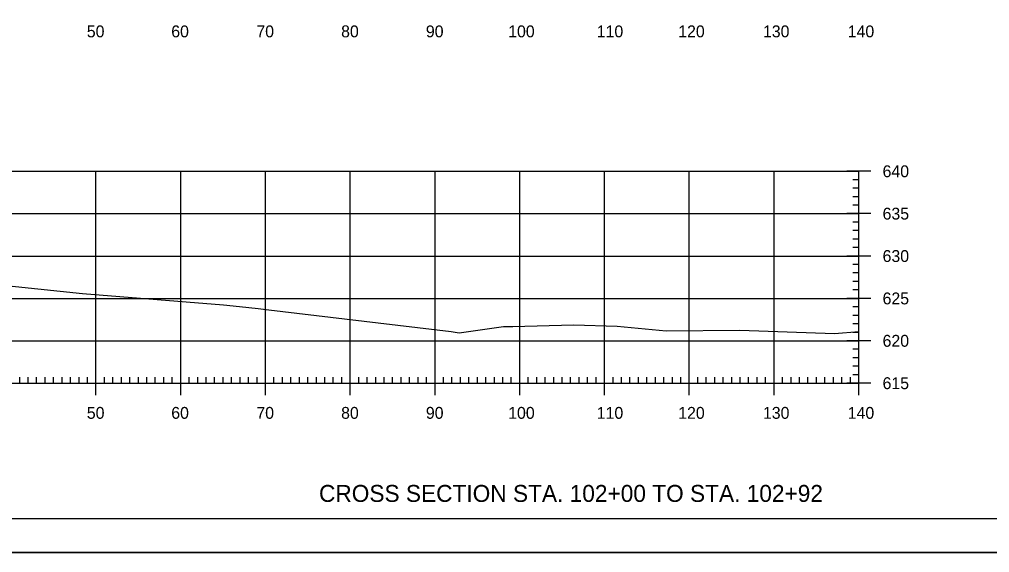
# Model space of a CAD drawing. Extents: x 1381471 to 1382703, y 370300 to 371487.
# Drawn here: x 1382177.6 to 1382292, y 370633.8 to 370696.7 of the extents above; entities that cross this region are included whole.
import ezdxf

# ---------------------------------------------------------------- set-up
doc = ezdxf.new("R2010")
doc.units = 0
doc.layers.add('Level 45', color=7, linetype='Continuous')

msp = doc.modelspace()

# ---------------------------------------------------------------- linework, layer by layer
at = {"layer": 'Level 45'}
for p, q in [((1381996.61, 370678.78), (1382276.61, 370678.78)), ((1382186.61, 370653.78), (1382186.61, 370678.78)), ((1382196.61, 370653.78), (1382196.61, 370678.78)), ((1382206.61, 370653.78), (1382206.61, 370678.78)), ((1382216.61, 370653.78), (1382216.61, 370678.78)), ((1382226.61, 370653.78), (1382226.61, 370678.78)), ((1382236.61, 370653.78), (1382236.61, 370678.78)), ((1382246.61, 370653.78), (1382246.61, 370678.78)), ((1382256.61, 370653.78), (1382256.61, 370678.78)), ((1382266.61, 370653.78), (1382266.61, 370678.78)), ((1382278.01, 370678.78), (1382275.21, 370678.78)), ((1382276.61, 370653.78), (1382276.61, 370678.78)), ((1382276.61, 370653.78), (1382276.61, 370678.78)), ((1382276.61, 370677.78), (1382275.91, 370677.78)), ((1382276.61, 370676.78), (1382275.91, 370676.78)), ((1382276.61, 370675.78), (1382275.91, 370675.78)), ((1382276.61, 370674.78), (1382275.91, 370674.78)), ((1381996.61, 370673.78), (1382276.61, 370673.78)), ((1382278.01, 370673.78), (1382275.21, 370673.78)), ((1382276.61, 370672.78), (1382275.91, 370672.78)), ((1382276.61, 370671.78), (1382275.91, 370671.78)), ((1382276.61, 370670.78), (1382275.91, 370670.78)), ((1382276.61, 370669.78), (1382275.91, 370669.78)), ((1381996.61, 370668.78), (1382276.61, 370668.78)), ((1382278.01, 370668.78), (1382275.21, 370668.78)), ((1382276.61, 370667.78), (1382275.91, 370667.78)), ((1382276.61, 370666.78), (1382275.91, 370666.78)), ((1382276.61, 370665.78), (1382275.91, 370665.78)), ((1382276.61, 370664.78), (1382275.91, 370664.78)), ((1381996.61, 370663.78), (1382276.61, 370663.78)), ((1382278.01, 370663.78), (1382275.21, 370663.78)), ((1382276.61, 370662.78), (1382275.91, 370662.78)), ((1382276.61, 370661.78), (1382275.91, 370661.78)), ((1382276.61, 370660.78), (1382275.91, 370660.78)), ((1382276.61, 370659.78), (1382275.91, 370659.78)), ((1381996.61, 370658.78), (1382276.61, 370658.78)), ((1382278.01, 370658.78), (1382275.21, 370658.78)), ((1382276.61, 370657.78), (1382275.91, 370657.78)), ((1382276.61, 370656.78), (1382275.91, 370656.78)), ((1382186.61, 370652.38), (1382186.61, 370655.18)), ((1382196.61, 370652.38), (1382196.61, 370655.18)), ((1382206.61, 370652.38), (1382206.61, 370655.18)), ((1382216.61, 370652.38), (1382216.61, 370655.18)), ((1382226.61, 370652.38), (1382226.61, 370655.18)), ((1382236.61, 370652.38), (1382236.61, 370655.18)), ((1382246.61, 370652.38), (1382246.61, 370655.18)), ((1382256.61, 370652.38), (1382256.61, 370655.18)), ((1382266.61, 370652.38), (1382266.61, 370655.18)), ((1382276.61, 370655.78), (1382275.91, 370655.78)), ((1382276.61, 370654.78), (1382275.91, 370654.78)), ((1382276.61, 370652.38), (1382276.61, 370655.18)), ((1381996.61, 370653.78), (1382276.61, 370653.78)), ((1381996.61, 370653.78), (1382276.61, 370653.78)), ((1382177.61, 370653.78), (1382177.61, 370654.48)), ((1382178.61, 370653.78), (1382178.61, 370654.48)), ((1382179.61, 370653.78), (1382179.61, 370654.48)), ((1382180.61, 370653.78), (1382180.61, 370654.48)), ((1382181.61, 370653.78), (1382181.61, 370654.48)), ((1382182.61, 370653.78), (1382182.61, 370654.48)), ((1382183.61, 370653.78), (1382183.61, 370654.48)), ((1382184.61, 370653.78), (1382184.61, 370654.48)), ((1382185.61, 370653.78), (1382185.61, 370654.48)), ((1382187.61, 370653.78), (1382187.61, 370654.48)), ((1382188.61, 370653.78), (1382188.61, 370654.48)), ((1382189.61, 370653.78), (1382189.61, 370654.48)), ((1382190.61, 370653.78), (1382190.61, 370654.48)), ((1382191.61, 370653.78), (1382191.61, 370654.48)), ((1382192.61, 370653.78), (1382192.61, 370654.48)), ((1382193.61, 370653.78), (1382193.61, 370654.48)), ((1382194.61, 370653.78), (1382194.61, 370654.48)), ((1382195.61, 370653.78), (1382195.61, 370654.48)), ((1382197.61, 370653.78), (1382197.61, 370654.48)), ((1382198.61, 370653.78), (1382198.61, 370654.48)), ((1382199.61, 370653.78), (1382199.61, 370654.48)), ((1382200.61, 370653.78), (1382200.61, 370654.48)), ((1382201.61, 370653.78), (1382201.61, 370654.48)), ((1382202.61, 370653.78), (1382202.61, 370654.48)), ((1382203.61, 370653.78), (1382203.61, 370654.48)), ((1382204.61, 370653.78), (1382204.61, 370654.48)), ((1382205.61, 370653.78), (1382205.61, 370654.48)), ((1382207.61, 370653.78), (1382207.61, 370654.48)), ((1382208.61, 370653.78), (1382208.61, 370654.48)), ((1382209.61, 370653.78), (1382209.61, 370654.48)), ((1382210.61, 370653.78), (1382210.61, 370654.48)), ((1382211.61, 370653.78), (1382211.61, 370654.48)), ((1382212.61, 370653.78), (1382212.61, 370654.48)), ((1382213.61, 370653.78), (1382213.61, 370654.48)), ((1382214.61, 370653.78), (1382214.61, 370654.48)), ((1382215.61, 370653.78), (1382215.61, 370654.48)), ((1382217.61, 370653.78), (1382217.61, 370654.48)), ((1382218.61, 370653.78), (1382218.61, 370654.48)), ((1382219.61, 370653.78), (1382219.61, 370654.48)), ((1382220.61, 370653.78), (1382220.61, 370654.48)), ((1382221.61, 370653.78), (1382221.61, 370654.48)), ((1382222.61, 370653.78), (1382222.61, 370654.48)), ((1382223.61, 370653.78), (1382223.61, 370654.48)), ((1382224.61, 370653.78), (1382224.61, 370654.48)), ((1382225.61, 370653.78), (1382225.61, 370654.48)), ((1382227.61, 370653.78), (1382227.61, 370654.48)), ((1382228.61, 370653.78), (1382228.61, 370654.48)), ((1382229.61, 370653.78), (1382229.61, 370654.48)), ((1382230.61, 370653.78), (1382230.61, 370654.48)), ((1382231.61, 370653.78), (1382231.61, 370654.48)), ((1382232.61, 370653.78), (1382232.61, 370654.48)), ((1382233.61, 370653.78), (1382233.61, 370654.48)), ((1382234.61, 370653.78), (1382234.61, 370654.48)), ((1382235.61, 370653.78), (1382235.61, 370654.48)), ((1382237.61, 370653.78), (1382237.61, 370654.48)), ((1382238.61, 370653.78), (1382238.61, 370654.48)), ((1382239.61, 370653.78), (1382239.61, 370654.48)), ((1382240.61, 370653.78), (1382240.61, 370654.48)), ((1382241.61, 370653.78), (1382241.61, 370654.48)), ((1382242.61, 370653.78), (1382242.61, 370654.48)), ((1382243.61, 370653.78), (1382243.61, 370654.48)), ((1382244.61, 370653.78), (1382244.61, 370654.48)), ((1382245.61, 370653.78), (1382245.61, 370654.48)), ((1382247.61, 370653.78), (1382247.61, 370654.48)), ((1382248.61, 370653.78), (1382248.61, 370654.48)), ((1382249.61, 370653.78), (1382249.61, 370654.48)), ((1382250.61, 370653.78), (1382250.61, 370654.48)), ((1382251.61, 370653.78), (1382251.61, 370654.48)), ((1382252.61, 370653.78), (1382252.61, 370654.48)), ((1382253.61, 370653.78), (1382253.61, 370654.48)), ((1382254.61, 370653.78), (1382254.61, 370654.48)), ((1382255.61, 370653.78), (1382255.61, 370654.48)), ((1382257.61, 370653.78), (1382257.61, 370654.48)), ((1382258.61, 370653.78), (1382258.61, 370654.48)), ((1382259.61, 370653.78), (1382259.61, 370654.48)), ((1382260.61, 370653.78), (1382260.61, 370654.48)), ((1382261.61, 370653.78), (1382261.61, 370654.48)), ((1382262.61, 370653.78), (1382262.61, 370654.48)), ((1382263.61, 370653.78), (1382263.61, 370654.48)), ((1382264.61, 370653.78), (1382264.61, 370654.48)), ((1382265.61, 370653.78), (1382265.61, 370654.48)), ((1382267.61, 370653.78), (1382267.61, 370654.48)), ((1382268.61, 370653.78), (1382268.61, 370654.48)), ((1382269.61, 370653.78), (1382269.61, 370654.48)), ((1382270.61, 370653.78), (1382270.61, 370654.48)), ((1382271.61, 370653.78), (1382271.61, 370654.48)), ((1382272.61, 370653.78), (1382272.61, 370654.48)), ((1382273.61, 370653.78), (1382273.61, 370654.48)), ((1382274.61, 370653.78), (1382274.61, 370654.48)), ((1382278.01, 370653.78), (1382275.21, 370653.78)), ((1382275.61, 370653.78), (1382275.61, 370654.48)), ((1382294.79, 370637.78), (1381978.61, 370637.78)), ((1381966.21, 370633.8), (1382299.55, 370633.8))]:
    msp.add_line(p, q, dxfattribs=at)
for points in [[(1381966.21, 370847.14), (1382299.55, 370847.14), (1382299.55, 370633.8), (1381966.21, 370633.8)], [(1382212.53, 370843.24), (1382232.15, 370843.24), (1382232.15, 370833.36), (1382248.27, 370833.36), (1382271.46, 370833.36), (1382271.46, 370809.03), (1382294.79, 370809.03), (1382294.79, 370637.78), (1381978.61, 370637.78), (1381978.61, 370843.24)]]:
    msp.add_lwpolyline(points, close=True, dxfattribs=at)
msp.add_lwpolyline([(1382171.79, 370665.74), (1382185.03, 370664.38), (1382201.66, 370663.01), (1382203.55, 370662.81), (1382205.73, 370662.58), (1382206.99, 370662.42), (1382215.92, 370661.39), (1382228.53, 370659.89), (1382229.45, 370659.72), (1382234.68, 370660.45), (1382235.77, 370660.48), (1382242.93, 370660.68), (1382248.11, 370660.51), (1382253.89, 370659.94), (1382262.55, 370660.03), (1382273.74, 370659.65), (1382276.61, 370659.86)], dxfattribs=at)

# ---------------------------------------------------------------- texts
for s, height, p in [('50', 1.4, (1382185.53, 370694.58)), ('60', 1.4, (1382195.49, 370694.58)), ('70', 1.4, (1382205.53, 370694.58)), ('80', 1.4, (1382215.53, 370694.58)), ('90', 1.4, (1382225.53, 370694.58)), ('100', 1.4, (1382235.24, 370694.58)), ('110', 1.4, (1382245.69, 370694.58)), ('120', 1.4, (1382255.3, 370694.58)), ('130', 1.4, (1382265.3, 370694.58)), ('140', 1.4, (1382275.3, 370694.58)), ('640', 1.4, (1382279.41, 370678.08)), ('635', 1.4, (1382279.41, 370673.08)), ('630', 1.4, (1382279.41, 370668.08)), ('625', 1.4, (1382279.41, 370663.08)), ('620', 1.4, (1382279.41, 370658.08)), ('615', 1.4, (1382279.41, 370653.08)), ('50', 1.4, (1382185.53, 370649.58)), ('60', 1.4, (1382195.49, 370649.58)), ('70', 1.4, (1382205.53, 370649.58)), ('80', 1.4, (1382215.53, 370649.58)), ('90', 1.4, (1382225.53, 370649.58)), ('100', 1.4, (1382235.24, 370649.58)), ('110', 1.4, (1382245.69, 370649.58)), ('120', 1.4, (1382255.3, 370649.58)), ('130', 1.4, (1382265.3, 370649.58)), ('140', 1.4, (1382275.3, 370649.58)), ('CROSS SECTION STA. 102+00 TO STA. 102+92', 2, (1382212.92, 370639.78))]:
    msp.add_text(s, height=height, dxfattribs=at).set_placement(p)

doc.saveas('drawing.dxf')
